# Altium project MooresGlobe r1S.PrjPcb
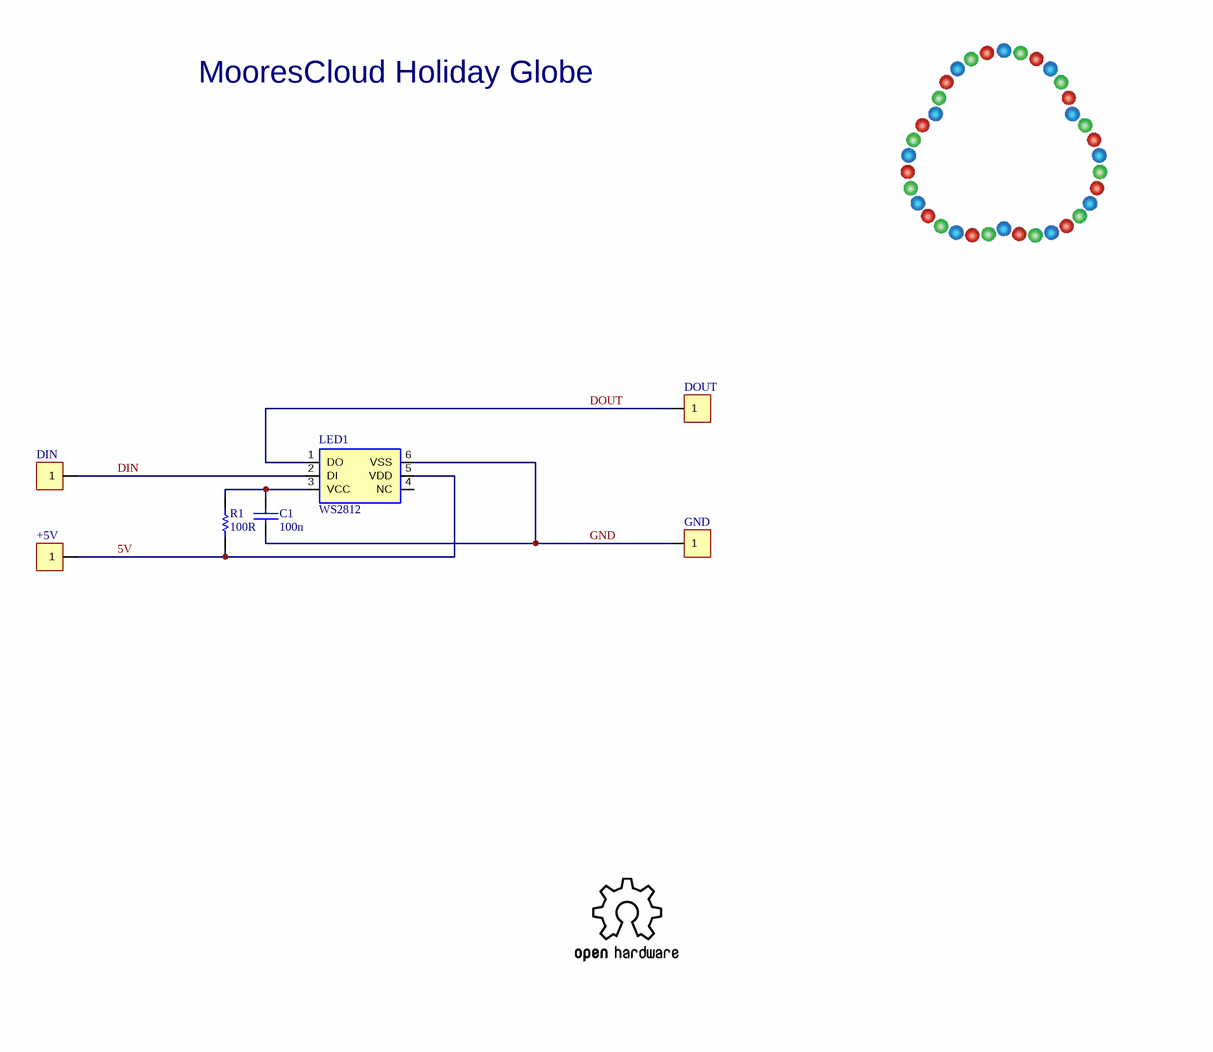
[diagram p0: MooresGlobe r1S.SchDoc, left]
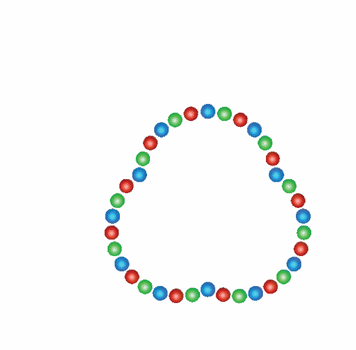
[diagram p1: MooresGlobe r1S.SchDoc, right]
1 sheet, 7 parts. Net scope: global (net labels, ports and power ports of the same name join across sheets).
Board files: MooresGlobe r1S.PcbDoc, MooresGlobe r1S Panel 10x10.PcbDoc, MooresGlobe r1S Panel 10x10 (no embed).PcbDoc

## Sheet MooresGlobe r1S.SchDoc: MooresGlobe for Holiday
size A4; DrawnBy: KJM; Organization: MooresCloud; Revision: 1S; SheetNumber: 1; SheetTotal: 1

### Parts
+5V  +5V  [Solder Pad]  (value not drawn)  (no BOM)
C1  100n  [ARA_0603]
DIN  DIN  [Solder Pad]  (value not drawn)  (no BOM)
DOUT  DOUT  [Solder Pad]  (value not drawn)  (no BOM)
GND  GND  [Solder Pad]  (value not drawn)  (no BOM)
LED1  WS2812  [PLCC6-IPC]
R1  100R  [ARA_0603]

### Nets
5V: +5V.1 LED1.5(VDD) R1.1
DIN: DIN.1 LED1.2(DI)
DOUT: DOUT.1 LED1.1(DO)
GND: C1.2 GND.1 LED1.6(VSS)
NetC1_1: C1.1 LED1.3(VCC) R1.2

Not connected (* = marked no-connect by the designer): LED1 4(NC)

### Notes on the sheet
- MooresCloud Holiday Globe

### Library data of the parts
+5V DIN DOUT GND = Solder Pad
C1 = CAP: Capacitor Ceramic 100n 50V Y5V 0603; 1.Manufacturer: Yageo; 4.CatNo: 311-1343-2-ND; 2.MfgNo: CC0603ZRY5V9BB104; 9.UnitCost: 0.00206
LED1 = WS2812: WorldSemi WS2812 Smart RGB LED; 4.CatNo: sc-WS2811-5050; 9.UnitCost: 0.15
R1 = Res Semi: Resistor 100R 0.1W 5% 0603; 1.Manufacturer: Yageo; 4.CatNo: 311-100GRTR-ND; 2.MfgNo: RC0603JR-07100RL; 9.UnitCost: 0.00092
